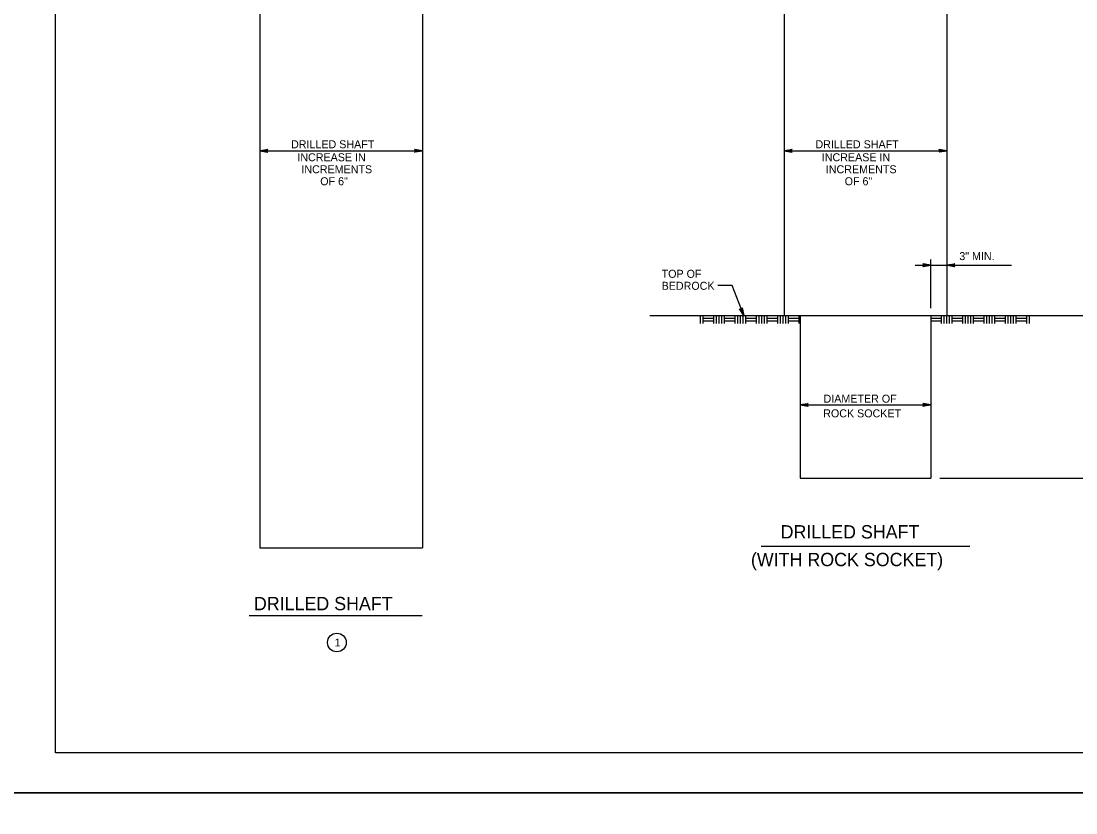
# Model space of a CAD drawing. Extents: x 646165 to 651486, y 296916 to 299292.
# Drawn here: x 649816.7 to 650212.1, y 297502.8 to 297799.8 of the extents above; entities that cross this region are included whole.
import ezdxf

# ---------------------------------------------------------------- set-up
doc = ezdxf.new("R2010")
doc.units = 0
for name, color, linetype in [('2', 7, 'Continuous'), ('51', 7, 'Continuous'), ('52', 7, 'Continuous'), ('53', 7, 'Continuous'), ('56', 7, 'Continuous'), ('PLT-BNDY', 7, 'Continuous')]:
    doc.layers.add(name, color=color, linetype=linetype)

msp = doc.modelspace()

# ---------------------------------------------------------------- linework, layer by layer
at = {"layer": '2'}
for p, q in [((649829.59, 297525.25), (649829.59, 298089.25)), ((650615.59, 297525.25), (649829.59, 297525.25))]:
    msp.add_line(p, q, dxfattribs=at)
at = {"layer": '51'}
for p, q in [((649906.2, 297832.98), (649906.2, 297602.22)), ((649967.2, 297832.98), (649967.2, 297602.22)), ((650102.8, 297832.98), (650102.8, 297689.26)), ((650163.8, 297832.98), (650163.8, 297689.26)), ((650102.8, 297689.26), (650108.8, 297689.26)), ((650108.8, 297689.26), (650108.8, 297628.26)), ((650157.8, 297689.26), (650157.8, 297628.26)), ((650157.8, 297689.26), (650163.8, 297689.26)), ((650108.8, 297628.26), (650157.8, 297628.26)), ((649906.2, 297602.22), (649967.2, 297602.22))]:
    msp.add_line(p, q, dxfattribs=at)
at = {"layer": '52'}
for p, q in [((649906.2, 297751.11), (649967.2, 297751.11)), ((650102.8, 297751.11), (650163.8, 297751.11)), ((650151.87, 297708.16), (650188.02, 297708.16)), ((650157.8, 297692.08), (650157.8, 297710.3)), ((650108.8, 297655.8), (650157.8, 297655.8)), ((650161.12, 297628.26), (650230.37, 297628.26))]:
    msp.add_line(p, q, dxfattribs=at)
for points in [[(649906.2, 297751.11), (649909.18, 297751.67), (649909.07, 297751.59), (649908.96, 297751.51), (649908.9, 297751.41), (649908.84, 297751.31), (649908.82, 297751.21), (649908.8, 297751.11), (649908.82, 297751.01), (649908.84, 297750.91), (649908.9, 297750.81), (649908.96, 297750.71), (649909.07, 297750.63), (649909.18, 297750.55), (649906.2, 297751.11), (649909.07, 297750.63), (649908.96, 297750.71), (649906.2, 297751.11), (649908.9, 297750.81), (649908.84, 297750.91), (649906.2, 297751.11), (649908.82, 297751.01), (649908.8, 297751.11), (649906.2, 297751.11), (649908.82, 297751.21), (649908.84, 297751.31), (649906.2, 297751.11), (649908.9, 297751.41), (649908.96, 297751.51), (649906.2, 297751.11), (649909.07, 297751.59)], [(649967.2, 297751.11), (649964.22, 297750.55), (649964.34, 297750.63), (649964.45, 297750.71), (649964.51, 297750.81), (649964.57, 297750.91), (649964.59, 297751.01), (649964.6, 297751.11), (649964.59, 297751.21), (649964.57, 297751.31), (649964.51, 297751.41), (649964.45, 297751.51), (649964.34, 297751.59), (649964.22, 297751.67), (649967.2, 297751.11), (649964.34, 297751.59), (649964.45, 297751.51), (649967.2, 297751.11), (649964.51, 297751.41), (649964.57, 297751.31), (649967.2, 297751.11), (649964.59, 297751.21), (649964.6, 297751.11), (649967.2, 297751.11), (649964.59, 297751.01), (649964.57, 297750.91), (649967.2, 297751.11), (649964.51, 297750.81), (649964.45, 297750.71), (649967.2, 297751.11), (649964.34, 297750.63)], [(650102.8, 297751.11), (650105.79, 297751.67), (650105.67, 297751.59), (650105.56, 297751.51), (650105.5, 297751.41), (650105.44, 297751.31), (650105.42, 297751.21), (650105.4, 297751.11), (650105.42, 297751.01), (650105.44, 297750.91), (650105.5, 297750.81), (650105.56, 297750.71), (650105.67, 297750.63), (650105.79, 297750.55), (650102.8, 297751.11), (650105.67, 297750.63), (650105.56, 297750.71), (650102.8, 297751.11), (650105.5, 297750.81), (650105.44, 297750.91), (650102.8, 297751.11), (650105.42, 297751.01), (650105.4, 297751.11), (650102.8, 297751.11), (650105.42, 297751.21), (650105.44, 297751.31), (650102.8, 297751.11), (650105.5, 297751.41), (650105.56, 297751.51), (650102.8, 297751.11), (650105.67, 297751.59)], [(650163.8, 297751.11), (650160.82, 297750.55), (650160.94, 297750.63), (650161.05, 297750.71), (650161.11, 297750.81), (650161.17, 297750.91), (650161.19, 297751.01), (650161.2, 297751.11), (650161.19, 297751.21), (650161.17, 297751.31), (650161.11, 297751.41), (650161.05, 297751.51), (650160.94, 297751.59), (650160.82, 297751.67), (650163.8, 297751.11), (650160.94, 297751.59), (650161.05, 297751.51), (650163.8, 297751.11), (650161.11, 297751.41), (650161.17, 297751.31), (650163.8, 297751.11), (650161.19, 297751.21), (650161.2, 297751.11), (650163.8, 297751.11), (650161.19, 297751.01), (650161.17, 297750.91), (650163.8, 297751.11), (650161.11, 297750.81), (650161.05, 297750.71), (650163.8, 297751.11), (650160.94, 297750.63)], [(650157.8, 297708.16), (650154.82, 297707.6), (650154.94, 297707.68), (650155.05, 297707.76), (650155.11, 297707.86), (650155.17, 297707.96), (650155.19, 297708.06), (650155.2, 297708.16), (650155.19, 297708.26), (650155.17, 297708.36), (650155.11, 297708.46), (650155.05, 297708.56), (650154.94, 297708.64), (650154.82, 297708.71), (650157.8, 297708.16), (650154.94, 297708.64), (650155.05, 297708.56), (650157.8, 297708.16), (650155.11, 297708.46), (650155.17, 297708.36), (650157.8, 297708.16), (650155.19, 297708.26), (650155.2, 297708.16), (650157.8, 297708.16), (650155.19, 297708.06), (650155.17, 297707.96), (650157.8, 297708.16), (650155.11, 297707.86), (650155.05, 297707.76), (650157.8, 297708.16), (650154.94, 297707.68)], [(650163.8, 297708.16), (650166.79, 297708.71), (650166.67, 297708.64), (650166.56, 297708.56), (650166.5, 297708.46), (650166.44, 297708.36), (650166.42, 297708.26), (650166.4, 297708.16), (650166.42, 297708.06), (650166.44, 297707.96), (650166.5, 297707.86), (650166.56, 297707.76), (650166.67, 297707.68), (650166.79, 297707.6), (650163.8, 297708.16), (650166.67, 297707.68), (650166.56, 297707.76), (650163.8, 297708.16), (650166.5, 297707.86), (650166.44, 297707.96), (650163.8, 297708.16), (650166.42, 297708.06), (650166.4, 297708.16), (650163.8, 297708.16), (650166.42, 297708.26), (650166.44, 297708.36), (650163.8, 297708.16), (650166.5, 297708.46), (650166.56, 297708.56), (650163.8, 297708.16), (650166.67, 297708.64)], [(650087.62, 297689.26), (650083.27, 297700.62), (650077.94, 297700.62)], [(650087.62, 297689.26), (650086.03, 297691.84), (650086.26, 297691.69), (650086.49, 297691.65), (650086.69, 297691.69), (650086.86, 297691.79), (650087.01, 297691.97), (650087.07, 297692.24), (650087.62, 297689.26), (650087.01, 297691.97), (650086.86, 297691.79), (650087.62, 297689.26), (650086.69, 297691.69), (650086.49, 297691.65), (650087.62, 297689.26), (650086.26, 297691.69)], [(650108.8, 297655.8), (650111.79, 297656.36), (650111.67, 297656.28), (650111.56, 297656.2), (650111.5, 297656.1), (650111.44, 297656), (650111.42, 297655.9), (650111.4, 297655.8), (650111.42, 297655.7), (650111.44, 297655.6), (650111.5, 297655.5), (650111.56, 297655.4), (650111.67, 297655.32), (650111.79, 297655.24), (650108.8, 297655.8), (650111.67, 297655.32), (650111.56, 297655.4), (650108.8, 297655.8), (650111.5, 297655.5), (650111.44, 297655.6), (650108.8, 297655.8), (650111.42, 297655.7), (650111.4, 297655.8), (650108.8, 297655.8), (650111.42, 297655.9), (650111.44, 297656), (650108.8, 297655.8), (650111.5, 297656.1), (650111.56, 297656.2), (650108.8, 297655.8), (650111.67, 297656.28)], [(650157.8, 297655.8), (650154.82, 297655.24), (650154.94, 297655.32), (650155.05, 297655.4), (650155.11, 297655.5), (650155.17, 297655.6), (650155.19, 297655.7), (650155.2, 297655.8), (650155.19, 297655.9), (650155.17, 297656), (650155.11, 297656.1), (650155.05, 297656.2), (650154.94, 297656.28), (650154.82, 297656.36), (650157.8, 297655.8), (650154.94, 297656.28), (650155.05, 297656.2), (650157.8, 297655.8), (650155.11, 297656.1), (650155.17, 297656), (650157.8, 297655.8), (650155.19, 297655.9), (650155.2, 297655.8), (650157.8, 297655.8), (650155.19, 297655.7), (650155.17, 297655.6), (650157.8, 297655.8), (650155.11, 297655.5), (650155.05, 297655.4), (650157.8, 297655.8), (650154.94, 297655.32)]]:
    msp.add_lwpolyline(points, dxfattribs=at)
msp.add_circle((649935.09, 297566.67), 3.5, dxfattribs=at)
at = {"layer": '53'}
for p, q in [((650094.13, 297602.85), (650172.37, 297602.85)), ((649902.27, 297576.82), (649967.08, 297576.82))]:
    msp.add_line(p, q, dxfattribs=at)
at = {"layer": '56'}
for p, q in [((650052.44, 297689.26), (650234, 297689.26)), ((650070.89, 297689.26), (650072.44, 297689.26)), ((650071.44, 297686.29), (650071.44, 297689.26)), ((650072.44, 297686.29), (650072.44, 297689.26)), ((650072.44, 297689.26), (650076.44, 297689.26)), ((650072.44, 297688.26), (650076.44, 297688.26)), ((650076.44, 297686.29), (650076.44, 297689.26)), ((650076.44, 297689.26), (650080.44, 297689.26)), ((650077.44, 297686.29), (650077.44, 297689.26)), ((650078.44, 297686.29), (650078.44, 297689.26)), ((650079.44, 297686.29), (650079.44, 297689.26)), ((650080.44, 297686.29), (650080.44, 297689.26)), ((650080.44, 297689.26), (650084.44, 297689.26)), ((650080.44, 297688.26), (650084.44, 297688.26)), ((650084.44, 297686.29), (650084.44, 297689.26)), ((650084.44, 297689.26), (650088.44, 297689.26)), ((650085.44, 297686.29), (650085.44, 297689.26)), ((650086.44, 297686.29), (650086.44, 297689.26)), ((650087.44, 297686.29), (650087.44, 297689.26)), ((650088.44, 297686.29), (650088.44, 297689.26)), ((650088.44, 297689.26), (650092.44, 297689.26)), ((650088.44, 297688.26), (650092.44, 297688.26)), ((650092.44, 297686.29), (650092.44, 297689.26)), ((650092.44, 297689.26), (650096.44, 297689.26)), ((650093.44, 297686.29), (650093.44, 297689.26)), ((650094.44, 297686.29), (650094.44, 297689.26)), ((650095.44, 297686.29), (650095.44, 297689.26)), ((650096.44, 297686.29), (650096.44, 297689.26)), ((650096.44, 297689.26), (650100.44, 297689.26)), ((650096.44, 297688.26), (650100.44, 297688.26)), ((650100.44, 297686.29), (650100.44, 297689.26)), ((650100.44, 297689.26), (650104.44, 297689.26)), ((650101.44, 297686.29), (650101.44, 297689.26)), ((650102.44, 297686.29), (650102.44, 297689.26)), ((650103.44, 297686.29), (650103.44, 297689.26)), ((650104.44, 297686.29), (650104.44, 297689.26)), ((650104.44, 297689.26), (650108.44, 297689.26)), ((650104.44, 297688.26), (650108.44, 297688.26)), ((650108.44, 297686.29), (650108.44, 297689.26)), ((650108.44, 297689.26), (650108.8, 297689.26)), ((650157.8, 297688.26), (650161.8, 297688.26)), ((650161.8, 297686.29), (650161.8, 297689.26)), ((650162.8, 297686.29), (650162.8, 297689.26)), ((650163.8, 297686.29), (650163.8, 297689.26)), ((650164.8, 297686.29), (650164.8, 297689.26)), ((650165.8, 297686.29), (650165.8, 297689.26)), ((650165.8, 297688.26), (650169.8, 297688.26)), ((650169.8, 297686.29), (650169.8, 297689.26)), ((650170.8, 297686.29), (650170.8, 297689.26)), ((650171.8, 297686.29), (650171.8, 297689.26)), ((650172.8, 297686.29), (650172.8, 297689.26)), ((650173.8, 297686.29), (650173.8, 297689.26)), ((650173.8, 297688.26), (650177.8, 297688.26)), ((650177.8, 297686.29), (650177.8, 297689.26)), ((650178.8, 297686.29), (650178.8, 297689.26)), ((650179.8, 297686.29), (650179.8, 297689.26)), ((650180.8, 297686.29), (650180.8, 297689.26)), ((650181.8, 297686.29), (650181.8, 297689.26)), ((650181.8, 297688.26), (650185.8, 297688.26)), ((650185.8, 297686.29), (650185.8, 297689.26)), ((650186.8, 297686.29), (650186.8, 297689.26)), ((650187.8, 297686.29), (650187.8, 297689.26)), ((650188.8, 297686.29), (650188.8, 297689.26)), ((650189.8, 297686.29), (650189.8, 297689.26)), ((650189.8, 297688.26), (650193.8, 297688.26)), ((650193.74, 297686.29), (650193.74, 297689.26)), ((650194.74, 297686.29), (650194.74, 297689.26)), ((650072.44, 297687.26), (650076.44, 297687.26)), ((650080.44, 297687.26), (650084.44, 297687.26)), ((650088.44, 297687.26), (650092.44, 297687.26)), ((650096.44, 297687.26), (650100.44, 297687.26)), ((650104.44, 297687.26), (650108.44, 297687.26)), ((650157.8, 297687.26), (650161.8, 297687.26)), ((650165.8, 297687.26), (650169.8, 297687.26)), ((650173.8, 297687.26), (650177.8, 297687.26)), ((650181.8, 297687.26), (650185.8, 297687.26)), ((650189.8, 297687.26), (650193.74, 297687.26))]:
    msp.add_line(p, q, dxfattribs=at)
at = {"layer": 'PLT-BNDY'}
for points in [[(649789.59, 298104.25), (650630.59, 298104.25), (650630.59, 297510.25), (649789.59, 297510.25)], [(649789.59, 297510.25), (650630.59, 297510.25), (650630.59, 296916.25), (649789.59, 296916.25)]]:
    msp.add_lwpolyline(points, close=True, dxfattribs=at)

# ---------------------------------------------------------------- texts
at = {"layer": '53'}
for s, height, p in [('DRILLED SHAFT', 3, (649917.91, 297752.04)), ('DRILLED SHAFT', 3, (650114.51, 297752.04)), ('INCREASE IN', 3, (649920.27, 297747.17)), ('INCREASE IN', 3, (650116.88, 297747.17)), ('INCREMENTS', 3, (649921.79, 297742.67)), ('INCREMENTS', 3, (650118.39, 297742.67)), ('OF 6"', 3, (649928.86, 297738.17)), ('OF 6"', 3, (650125.46, 297738.17)), ('3" MIN.', 3, (650168.43, 297710.1)), ('TOP OF', 3, (650056.84, 297703.46)), ('BEDROCK', 3, (650056.84, 297698.96)), ('DIAMETER OF', 3, (650117.54, 297656.62)), ('ROCK SOCKET', 3, (650117.41, 297651.12)), ('DRILLED SHAFT', 5, (650101.45, 297605.68)), ('(WITH ROCK SOCKET)', 5, (650090.31, 297595.3)), ('DRILLED SHAFT', 5, (649903.98, 297578.76)), ('1', 3, (649934.25, 297565.17))]:
    msp.add_text(s, height=height, dxfattribs=at).set_placement(p)

doc.saveas('drawing.dxf')
